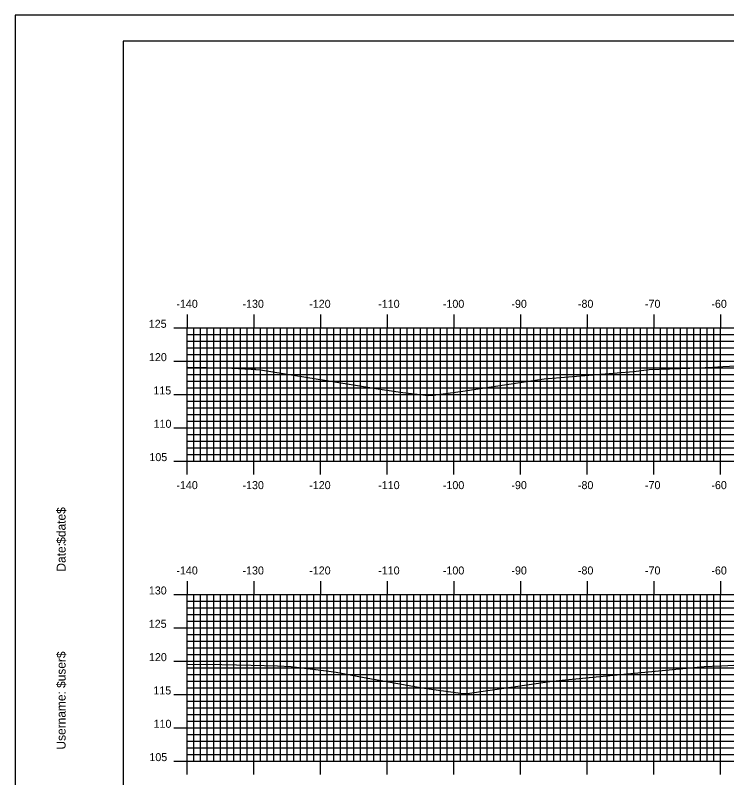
# Model space of a CAD drawing. Extents: x 844536 to 844879, y 363538 to 363758.
# Drawn here: x 844536.2 to 844642.9, y 363643.2 to 363757.6 of the extents above; entities that cross this region are included whole.
import ezdxf

# ---------------------------------------------------------------- set-up
doc = ezdxf.new("R2010")
doc.units = 0
for name, color, linetype in [('BORDER', 7, 'Continuous'), ('H_V ANNOTATION', 7, 'Continuous'), ('MAJOR', 7, 'Continuous'), ('MINOR', 7, 'Continuous'), ('PLOT BOUNDARY', 7, 'Continuous'), ('S_Roadway_Centerline', 7, 'Continuous')]:
    doc.layers.add(name, color=color, linetype=linetype)

msp = doc.modelspace()

# ---------------------------------------------------------------- linework, layer by layer
at = {"layer": 'BORDER'}
msp.add_lwpolyline([(844552.36, 363543.72), (844872.36, 363543.72), (844872.36, 363753.72), (844552.36, 363753.72)], close=True, dxfattribs=at)
at = {"layer": 'MAJOR'}
for p, q in [((844561.96, 363712.73), (844561.96, 363710.72)), ((844571.96, 363712.73), (844571.96, 363710.72)), ((844581.96, 363712.73), (844581.96, 363710.72)), ((844591.96, 363712.73), (844591.96, 363710.72)), ((844601.96, 363712.73), (844601.96, 363710.72)), ((844611.96, 363712.73), (844611.96, 363710.72)), ((844621.96, 363712.73), (844621.96, 363710.72)), ((844631.96, 363712.73), (844631.96, 363710.72)), ((844641.96, 363712.73), (844641.96, 363710.72)), ((844559.96, 363710.72), (844561.96, 363710.72)), ((844561.96, 363710.72), (844841.96, 363710.72)), ((844561.96, 363690.72), (844561.96, 363710.72)), ((844561.96, 363690.72), (844561.96, 363710.72)), ((844561.96, 363710.72), (844841.96, 363710.72)), ((844571.96, 363690.72), (844571.96, 363710.72)), ((844581.96, 363690.72), (844581.96, 363710.72)), ((844591.96, 363690.72), (844591.96, 363710.72)), ((844601.96, 363690.72), (844601.96, 363710.72)), ((844611.96, 363690.72), (844611.96, 363710.72)), ((844621.96, 363690.72), (844621.96, 363710.72)), ((844631.96, 363690.72), (844631.96, 363710.72)), ((844641.96, 363690.72), (844641.96, 363710.72)), ((844559.96, 363705.72), (844561.96, 363705.72)), ((844561.96, 363705.72), (844841.96, 363705.72)), ((844559.96, 363700.72), (844561.96, 363700.72)), ((844561.96, 363700.72), (844841.96, 363700.72)), ((844559.96, 363695.72), (844561.96, 363695.72)), ((844561.96, 363695.72), (844841.96, 363695.72)), ((844559.96, 363690.72), (844561.96, 363690.72)), ((844561.96, 363690.72), (844841.96, 363690.72)), ((844561.96, 363690.72), (844841.96, 363690.72)), ((844561.96, 363688.72), (844561.96, 363690.72)), ((844571.96, 363688.72), (844571.96, 363690.72)), ((844581.96, 363688.72), (844581.96, 363690.72)), ((844591.96, 363688.72), (844591.96, 363690.72)), ((844601.96, 363688.72), (844601.96, 363690.72)), ((844611.96, 363688.72), (844611.96, 363690.72)), ((844621.96, 363688.72), (844621.96, 363690.72)), ((844631.96, 363688.72), (844631.96, 363690.72)), ((844641.96, 363688.72), (844641.96, 363690.72)), ((844561.96, 363672.73), (844561.96, 363670.72)), ((844571.96, 363672.73), (844571.96, 363670.72)), ((844581.96, 363672.73), (844581.96, 363670.72)), ((844591.96, 363672.73), (844591.96, 363670.72)), ((844601.96, 363672.73), (844601.96, 363670.72)), ((844611.96, 363672.73), (844611.96, 363670.72)), ((844621.96, 363672.73), (844621.96, 363670.72)), ((844631.96, 363672.73), (844631.96, 363670.72)), ((844641.96, 363672.73), (844641.96, 363670.72)), ((844559.96, 363670.72), (844561.96, 363670.72)), ((844561.96, 363670.72), (844841.96, 363670.72)), ((844561.96, 363645.72), (844561.96, 363670.72)), ((844561.96, 363645.72), (844561.96, 363670.72)), ((844561.96, 363670.72), (844841.96, 363670.72)), ((844571.96, 363645.72), (844571.96, 363670.72)), ((844581.96, 363645.72), (844581.96, 363670.72)), ((844591.96, 363645.72), (844591.96, 363670.72)), ((844601.96, 363645.72), (844601.96, 363670.72)), ((844611.96, 363645.72), (844611.96, 363670.72)), ((844621.96, 363645.72), (844621.96, 363670.72)), ((844631.96, 363645.72), (844631.96, 363670.72)), ((844641.96, 363645.72), (844641.96, 363670.72)), ((844559.96, 363665.72), (844561.96, 363665.72)), ((844561.96, 363665.72), (844841.96, 363665.72)), ((844559.96, 363660.72), (844561.96, 363660.72)), ((844561.96, 363660.72), (844841.96, 363660.72)), ((844559.96, 363655.72), (844561.96, 363655.72)), ((844561.96, 363655.72), (844841.96, 363655.72)), ((844559.96, 363650.72), (844561.96, 363650.72)), ((844561.96, 363650.72), (844841.96, 363650.72)), ((844559.96, 363645.72), (844561.96, 363645.72)), ((844561.96, 363645.72), (844841.96, 363645.72)), ((844561.96, 363645.72), (844841.96, 363645.72)), ((844561.96, 363643.72), (844561.96, 363645.72)), ((844571.96, 363643.72), (844571.96, 363645.72)), ((844581.96, 363643.72), (844581.96, 363645.72)), ((844591.96, 363643.72), (844591.96, 363645.72)), ((844601.96, 363643.72), (844601.96, 363645.72)), ((844611.96, 363643.72), (844611.96, 363645.72)), ((844621.96, 363643.72), (844621.96, 363645.72)), ((844631.96, 363643.72), (844631.96, 363645.72)), ((844641.96, 363643.72), (844641.96, 363645.72))]:
    msp.add_line(p, q, dxfattribs=at)
at = {"layer": 'MINOR'}
for p, q in [((844562.96, 363690.72), (844562.96, 363710.72)), ((844563.96, 363690.72), (844563.96, 363710.72)), ((844564.96, 363690.72), (844564.96, 363710.72)), ((844565.96, 363690.72), (844565.96, 363710.72)), ((844566.96, 363690.72), (844566.96, 363710.72)), ((844567.96, 363690.72), (844567.96, 363710.72)), ((844568.96, 363690.72), (844568.96, 363710.72)), ((844569.96, 363690.72), (844569.96, 363710.72)), ((844570.96, 363690.72), (844570.96, 363710.72)), ((844572.96, 363690.72), (844572.96, 363710.72)), ((844573.96, 363690.72), (844573.96, 363710.72)), ((844574.96, 363690.72), (844574.96, 363710.72)), ((844575.96, 363690.72), (844575.96, 363710.72)), ((844576.96, 363690.72), (844576.96, 363710.72)), ((844577.96, 363690.72), (844577.96, 363710.72)), ((844578.96, 363690.72), (844578.96, 363710.72)), ((844579.96, 363690.72), (844579.96, 363710.72)), ((844580.96, 363690.72), (844580.96, 363710.72)), ((844582.96, 363690.72), (844582.96, 363710.72)), ((844583.96, 363690.72), (844583.96, 363710.72)), ((844584.96, 363690.72), (844584.96, 363710.72)), ((844585.96, 363690.72), (844585.96, 363710.72)), ((844586.96, 363690.72), (844586.96, 363710.72)), ((844587.96, 363690.72), (844587.96, 363710.72)), ((844588.96, 363690.72), (844588.96, 363710.72)), ((844589.96, 363690.72), (844589.96, 363710.72)), ((844590.96, 363690.72), (844590.96, 363710.72)), ((844592.96, 363690.72), (844592.96, 363710.72)), ((844593.96, 363690.72), (844593.96, 363710.72)), ((844594.96, 363690.72), (844594.96, 363710.72)), ((844595.96, 363690.72), (844595.96, 363710.72)), ((844596.96, 363690.72), (844596.96, 363710.72)), ((844597.96, 363690.72), (844597.96, 363710.72)), ((844598.96, 363690.72), (844598.96, 363710.72)), ((844599.96, 363690.72), (844599.96, 363710.72)), ((844600.96, 363690.72), (844600.96, 363710.72)), ((844602.96, 363690.72), (844602.96, 363710.72)), ((844603.96, 363690.72), (844603.96, 363710.72)), ((844604.96, 363690.72), (844604.96, 363710.72)), ((844605.96, 363690.72), (844605.96, 363710.72)), ((844606.96, 363690.72), (844606.96, 363710.72)), ((844607.96, 363690.72), (844607.96, 363710.72)), ((844608.96, 363690.72), (844608.96, 363710.72)), ((844609.96, 363690.72), (844609.96, 363710.72)), ((844610.96, 363690.72), (844610.96, 363710.72)), ((844612.96, 363690.72), (844612.96, 363710.72)), ((844613.96, 363690.72), (844613.96, 363710.72)), ((844614.96, 363690.72), (844614.96, 363710.72)), ((844615.96, 363690.72), (844615.96, 363710.72)), ((844616.96, 363690.72), (844616.96, 363710.72)), ((844617.96, 363690.72), (844617.96, 363710.72)), ((844618.96, 363690.72), (844618.96, 363710.72)), ((844619.96, 363690.72), (844619.96, 363710.72)), ((844620.96, 363690.72), (844620.96, 363710.72)), ((844622.96, 363690.72), (844622.96, 363710.72)), ((844623.96, 363690.72), (844623.96, 363710.72)), ((844624.96, 363690.72), (844624.96, 363710.72)), ((844625.96, 363690.72), (844625.96, 363710.72)), ((844626.96, 363690.72), (844626.96, 363710.72)), ((844627.96, 363690.72), (844627.96, 363710.72)), ((844628.96, 363690.72), (844628.96, 363710.72)), ((844629.96, 363690.72), (844629.96, 363710.72)), ((844630.96, 363690.72), (844630.96, 363710.72)), ((844632.96, 363690.72), (844632.96, 363710.72)), ((844633.96, 363690.72), (844633.96, 363710.72)), ((844634.96, 363690.72), (844634.96, 363710.72)), ((844635.96, 363690.72), (844635.96, 363710.72)), ((844636.96, 363690.72), (844636.96, 363710.72)), ((844637.96, 363690.72), (844637.96, 363710.72)), ((844638.96, 363690.72), (844638.96, 363710.72)), ((844639.96, 363690.72), (844639.96, 363710.72)), ((844640.96, 363690.72), (844640.96, 363710.72)), ((844561.96, 363709.72), (844841.96, 363709.72)), ((844561.96, 363709.72), (844563.97, 363709.72)), ((844561.96, 363708.72), (844841.96, 363708.72)), ((844561.96, 363708.72), (844563.97, 363708.72)), ((844561.96, 363707.72), (844841.96, 363707.72)), ((844561.96, 363707.72), (844563.97, 363707.72)), ((844561.96, 363706.72), (844841.96, 363706.72)), ((844561.96, 363706.72), (844563.97, 363706.72)), ((844561.96, 363704.72), (844841.96, 363704.72)), ((844561.96, 363704.72), (844563.97, 363704.72)), ((844561.96, 363703.72), (844841.96, 363703.72)), ((844561.96, 363703.72), (844563.97, 363703.72)), ((844561.96, 363702.72), (844841.96, 363702.72)), ((844561.96, 363702.72), (844563.97, 363702.72)), ((844561.96, 363701.72), (844841.96, 363701.72)), ((844561.96, 363701.72), (844563.97, 363701.72)), ((844561.96, 363699.72), (844841.96, 363699.72)), ((844561.96, 363699.72), (844563.97, 363699.72)), ((844561.96, 363698.72), (844841.96, 363698.72)), ((844561.96, 363698.72), (844563.97, 363698.72)), ((844561.96, 363697.72), (844841.96, 363697.72)), ((844561.96, 363697.72), (844563.97, 363697.72)), ((844561.96, 363696.72), (844841.96, 363696.72)), ((844561.96, 363696.72), (844563.97, 363696.72)), ((844561.96, 363694.72), (844841.96, 363694.72)), ((844561.96, 363694.72), (844563.97, 363694.72)), ((844561.96, 363693.72), (844841.96, 363693.72)), ((844561.96, 363693.72), (844563.97, 363693.72)), ((844561.96, 363692.72), (844841.96, 363692.72)), ((844561.96, 363692.72), (844563.97, 363692.72)), ((844561.96, 363691.72), (844841.96, 363691.72)), ((844561.96, 363691.72), (844563.97, 363691.72)), ((844562.96, 363645.72), (844562.96, 363670.72)), ((844563.96, 363645.72), (844563.96, 363670.72)), ((844564.96, 363645.72), (844564.96, 363670.72)), ((844565.96, 363645.72), (844565.96, 363670.72)), ((844566.96, 363645.72), (844566.96, 363670.72)), ((844567.96, 363645.72), (844567.96, 363670.72)), ((844568.96, 363645.72), (844568.96, 363670.72)), ((844569.96, 363645.72), (844569.96, 363670.72)), ((844570.96, 363645.72), (844570.96, 363670.72)), ((844572.96, 363645.72), (844572.96, 363670.72)), ((844573.96, 363645.72), (844573.96, 363670.72)), ((844574.96, 363645.72), (844574.96, 363670.72)), ((844575.96, 363645.72), (844575.96, 363670.72)), ((844576.96, 363645.72), (844576.96, 363670.72)), ((844577.96, 363645.72), (844577.96, 363670.72)), ((844578.96, 363645.72), (844578.96, 363670.72)), ((844579.96, 363645.72), (844579.96, 363670.72)), ((844580.96, 363645.72), (844580.96, 363670.72)), ((844582.96, 363645.72), (844582.96, 363670.72)), ((844583.96, 363645.72), (844583.96, 363670.72)), ((844584.96, 363645.72), (844584.96, 363670.72)), ((844585.96, 363645.72), (844585.96, 363670.72)), ((844586.96, 363645.72), (844586.96, 363670.72)), ((844587.96, 363645.72), (844587.96, 363670.72)), ((844588.96, 363645.72), (844588.96, 363670.72)), ((844589.96, 363645.72), (844589.96, 363670.72)), ((844590.96, 363645.72), (844590.96, 363670.72)), ((844592.96, 363645.72), (844592.96, 363670.72)), ((844593.96, 363645.72), (844593.96, 363670.72)), ((844594.96, 363645.72), (844594.96, 363670.72)), ((844595.96, 363645.72), (844595.96, 363670.72)), ((844596.96, 363645.72), (844596.96, 363670.72)), ((844597.96, 363645.72), (844597.96, 363670.72)), ((844598.96, 363645.72), (844598.96, 363670.72)), ((844599.96, 363645.72), (844599.96, 363670.72)), ((844600.96, 363645.72), (844600.96, 363670.72)), ((844602.96, 363645.72), (844602.96, 363670.72)), ((844603.96, 363645.72), (844603.96, 363670.72)), ((844604.96, 363645.72), (844604.96, 363670.72)), ((844605.96, 363645.72), (844605.96, 363670.72)), ((844606.96, 363645.72), (844606.96, 363670.72)), ((844607.96, 363645.72), (844607.96, 363670.72)), ((844608.96, 363645.72), (844608.96, 363670.72)), ((844609.96, 363645.72), (844609.96, 363670.72)), ((844610.96, 363645.72), (844610.96, 363670.72)), ((844612.96, 363645.72), (844612.96, 363670.72)), ((844613.96, 363645.72), (844613.96, 363670.72)), ((844614.96, 363645.72), (844614.96, 363670.72)), ((844615.96, 363645.72), (844615.96, 363670.72)), ((844616.96, 363645.72), (844616.96, 363670.72)), ((844617.96, 363645.72), (844617.96, 363670.72)), ((844618.96, 363645.72), (844618.96, 363670.72)), ((844619.96, 363645.72), (844619.96, 363670.72)), ((844620.96, 363645.72), (844620.96, 363670.72)), ((844622.96, 363645.72), (844622.96, 363670.72)), ((844623.96, 363645.72), (844623.96, 363670.72)), ((844624.96, 363645.72), (844624.96, 363670.72)), ((844625.96, 363645.72), (844625.96, 363670.72)), ((844626.96, 363645.72), (844626.96, 363670.72)), ((844627.96, 363645.72), (844627.96, 363670.72)), ((844628.96, 363645.72), (844628.96, 363670.72)), ((844629.96, 363645.72), (844629.96, 363670.72)), ((844630.96, 363645.72), (844630.96, 363670.72)), ((844632.96, 363645.72), (844632.96, 363670.72)), ((844633.96, 363645.72), (844633.96, 363670.72)), ((844634.96, 363645.72), (844634.96, 363670.72)), ((844635.96, 363645.72), (844635.96, 363670.72)), ((844636.96, 363645.72), (844636.96, 363670.72)), ((844637.96, 363645.72), (844637.96, 363670.72)), ((844638.96, 363645.72), (844638.96, 363670.72)), ((844639.96, 363645.72), (844639.96, 363670.72)), ((844640.96, 363645.72), (844640.96, 363670.72)), ((844561.96, 363669.72), (844841.96, 363669.72)), ((844561.96, 363669.72), (844563.97, 363669.72)), ((844561.96, 363668.72), (844841.96, 363668.72)), ((844561.96, 363668.72), (844563.97, 363668.72)), ((844561.96, 363667.72), (844841.96, 363667.72)), ((844561.96, 363667.72), (844563.97, 363667.72)), ((844561.96, 363666.72), (844841.96, 363666.72)), ((844561.96, 363666.72), (844563.97, 363666.72)), ((844561.96, 363664.72), (844841.96, 363664.72)), ((844561.96, 363664.72), (844563.97, 363664.72)), ((844561.96, 363663.72), (844841.96, 363663.72)), ((844561.96, 363663.72), (844563.97, 363663.72)), ((844561.96, 363662.72), (844841.96, 363662.72)), ((844561.96, 363662.72), (844563.97, 363662.72)), ((844561.96, 363661.72), (844841.96, 363661.72)), ((844561.96, 363661.72), (844563.97, 363661.72)), ((844561.96, 363659.72), (844841.96, 363659.72)), ((844561.96, 363659.72), (844563.97, 363659.72)), ((844561.96, 363658.72), (844841.96, 363658.72)), ((844561.96, 363658.72), (844563.97, 363658.72)), ((844561.96, 363657.72), (844841.96, 363657.72)), ((844561.96, 363657.72), (844563.97, 363657.72)), ((844561.96, 363656.72), (844841.96, 363656.72)), ((844561.96, 363656.72), (844563.97, 363656.72)), ((844561.96, 363654.72), (844841.96, 363654.72)), ((844561.96, 363654.72), (844563.97, 363654.72)), ((844561.96, 363653.72), (844841.96, 363653.72)), ((844561.96, 363653.72), (844563.97, 363653.72)), ((844561.96, 363652.72), (844841.96, 363652.72)), ((844561.96, 363652.72), (844563.97, 363652.72)), ((844561.96, 363651.72), (844841.96, 363651.72)), ((844561.96, 363651.72), (844563.97, 363651.72)), ((844561.96, 363649.72), (844841.96, 363649.72)), ((844561.96, 363649.72), (844563.97, 363649.72)), ((844561.96, 363648.72), (844841.96, 363648.72)), ((844561.96, 363648.72), (844563.97, 363648.72)), ((844561.96, 363647.72), (844841.96, 363647.72)), ((844561.96, 363647.72), (844563.97, 363647.72)), ((844561.96, 363646.72), (844841.96, 363646.72)), ((844561.96, 363646.72), (844563.97, 363646.72))]:
    msp.add_line(p, q, dxfattribs=at)
at = {"layer": 'PLOT BOUNDARY'}
msp.add_lwpolyline([(844536.18, 363537.6), (844876.18, 363537.6), (844876.18, 363757.6), (844536.18, 363757.6)], close=True, dxfattribs=at)
at = {"layer": 'S_Roadway_Centerline'}
for points in [[(844561.96, 363704.8), (844562.05, 363704.8), (844567.72, 363704.71), (844571.56, 363704.53), (844572.17, 363704.5), (844572.23, 363704.49), (844572.97, 363704.4), (844591.24, 363701.49), (844594.3, 363701), (844598.17, 363700.59), (844598.93, 363700.61), (844603.33, 363701.2), (844607.55, 363701.88), (844615.51, 363703.06), (844626.48, 363703.96), (844628.92, 363704.19), (844631.29, 363704.49), (844637.36, 363704.69), (844640.83, 363704.83), (844642.31, 363704.92), (844644.33, 363705.02)], [(844561.96, 363660.27), (844567.18, 363660.2), (844571.55, 363660.11), (844575.53, 363660), (844577.56, 363659.9), (844583.2, 363659.2), (844584.32, 363659.05), (844588.5, 363658.27), (844597.22, 363656.73), (844599.69, 363656.37), (844602.97, 363655.91), (844603.97, 363655.89), (844616.36, 363657.66), (844618.25, 363657.87), (844621.79, 363658.24), (844637.4, 363659.7), (844639.53, 363659.93), (844640.74, 363659.97), (844642.11, 363660.04), (844646.78, 363660.26)]]:
    msp.add_lwpolyline(points, dxfattribs=at)

# ---------------------------------------------------------------- texts
at = {"layer": 'BORDER'}
for s, p in [('$date$', (844543.73, 363678.33)), ('Date:', (844543.73, 363674.15)), ('$user$', (844543.73, 363656.7)), ('Username:', (844543.73, 363647.46))]:
    msp.add_text(s, height=1.339, rotation=90, dxfattribs=at).set_placement(p)
at = {"layer": 'H_V ANNOTATION'}
for s, p in [('-140', (844560.35, 363713.72)), ('-130', (844570.27, 363713.72)), ('-120', (844580.28, 363713.72)), ('-110', (844590.63, 363713.72)), ('-100', (844600.33, 363713.72)), ('-90', (844610.61, 363713.72)), ('-80', (844620.59, 363713.72)), ('-70', (844630.65, 363713.72)), ('-60', (844640.61, 363713.72)), ('125', (844556.21, 363710.72)), ('120', (844556.24, 363705.72)), ('115', (844556.9, 363700.72)), ('110', (844556.93, 363695.72)), ('105', (844556.3, 363690.72)), ('-140', (844560.35, 363686.52)), ('-130', (844570.27, 363686.52)), ('-120', (844580.28, 363686.52)), ('-110', (844590.63, 363686.52)), ('-100', (844600.33, 363686.52)), ('-90', (844610.61, 363686.52)), ('-80', (844620.59, 363686.52)), ('-70', (844630.65, 363686.52)), ('-60', (844640.61, 363686.52)), ('-140', (844560.35, 363673.72)), ('-130', (844570.27, 363673.72)), ('-120', (844580.28, 363673.72)), ('-110', (844590.63, 363673.72)), ('-100', (844600.33, 363673.72)), ('-90', (844610.61, 363673.72)), ('-80', (844620.59, 363673.72)), ('-70', (844630.65, 363673.72)), ('-60', (844640.61, 363673.72)), ('130', (844556.22, 363670.72)), ('125', (844556.21, 363665.72)), ('120', (844556.24, 363660.72)), ('115', (844556.9, 363655.72)), ('110', (844556.93, 363650.72)), ('105', (844556.3, 363645.72))]:
    msp.add_text(s, height=1.2, dxfattribs=at).set_placement(p)
at = {"layer": 'MAJOR'}
for p in [(844561.95, 363690.72), (844561.95, 363645.72)]:
    msp.add_text('-', height=0.012, dxfattribs=at).set_placement(p)

doc.saveas('drawing.dxf')
